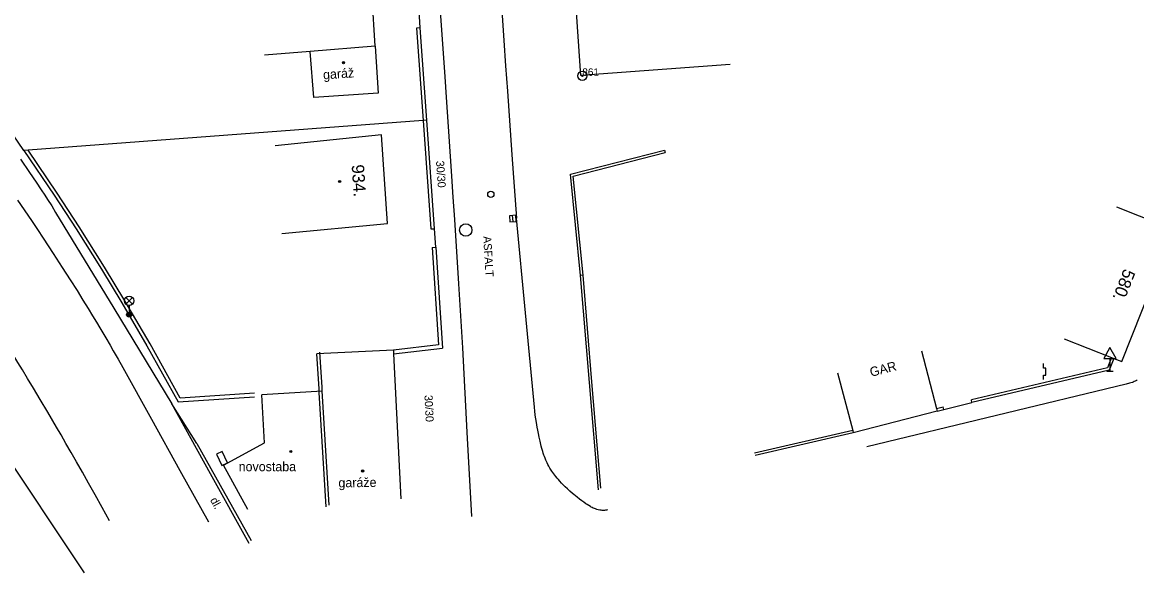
# Model space of a CAD drawing. Extents: x -538441 to -536770, y -1181008 to -1179809.
# Drawn here: x -538072 to -537982.2, y -1180978.1 to -1180933.7 of the extents above; entities that cross this region are included whole.
import ezdxf

# ---------------------------------------------------------------- set-up
doc = ezdxf.new("R2010")
doc.units = 0
for name, color, linetype in [('Vrstva 10', 7, 'Continuous'), ('Vrstva 11', 7, 'Continuous'), ('Vrstva 21', 7, 'Continuous'), ('Vrstva 23', 7, 'Continuous'), ('Vrstva 24', 7, 'Continuous'), ('Vrstva 27', 7, 'Continuous'), ('Vrstva 28', 7, 'Continuous'), ('Vrstva 33', 7, 'Continuous'), ('Vrstva 34', 7, 'Continuous'), ('Vrstva 39', 7, 'Continuous'), ('Vrstva 40', 7, 'Continuous'), ('Vrstva 41', 7, 'Continuous'), ('Vrstva 47', 7, 'Continuous'), ('Vrstva 5', 7, 'Continuous'), ('Vrstva 7', 7, 'Continuous'), ('Vrstva 8', 7, 'Continuous')]:
    doc.layers.add(name, color=color, linetype=linetype)

msp = doc.modelspace()

# ---------------------------------------------------------------- linework, layer by layer
at = {"layer": 'Vrstva 10'}
for p, q in [((-538037.959, -1180937.728), (-538038.567, -1180929.21)), ((-538037.788, -1180940.162), (-538037.959, -1180937.728)), ((-538032.92, -1180939.28), (-538032.555, -1180944.4)), ((-538032.555, -1180944.4), (-538032.19, -1180949.52)), ((-538036.84, -1180954.79), (-538037.16, -1180949.63)), ((-538031.465, -1180957.135), (-538032.19, -1180949.52)), ((-538036.52, -1180959.95), (-538036.84, -1180954.79)), ((-538030.74, -1180964.75), (-538031.465, -1180957.135)), ((-538036.15, -1180966.75), (-538036.52, -1180959.95)), ((-537983.08, -1180962.88), (-537993.522, -1180965.412)), ((-537993.522, -1180965.412), (-538003.965, -1180967.945)), ((-538066.98, -1180978.07), (-538074.76, -1180966.42)), ((-538035.78, -1180973.55), (-538036.15, -1180966.75))]:
    msp.add_line(p, q, dxfattribs=at)
for points in [[(-538033.479, -1180931.117), (-538033.204, -1180935.199), (-538033.064, -1180937.239), (-538032.92, -1180939.28)], [(-538037.16, -1180949.63), (-538037.274, -1180947.821), (-538037.384, -1180946.124), (-538037.596, -1180942.944), (-538037.788, -1180940.162)], [(-538072.37, -1180948.052), (-538071.258, -1180949.708), (-538070.775, -1180950.434)], [(-538070.775, -1180950.434), (-538070.323, -1180951.115), (-538069.901, -1180951.755), (-538069.507, -1180952.356), (-538068.774, -1180953.486), (-538068.138, -1180954.478), (-538067.587, -1180955.349), (-538067.109, -1180956.114), (-538066.694, -1180956.785), (-538066.334, -1180957.374), (-538066.021, -1180957.891), (-538065.749, -1180958.344)], [(-538069.238, -1180966.337), (-538069.936, -1180965.149), (-538070.551, -1180964.112), (-538071.093, -1180963.208), (-538071.571, -1180962.418), (-538071.991, -1180961.728), (-538072.361, -1180961.126), (-538073.012, -1180960.074), (-538073.504, -1180959.288), (-538073.876, -1180958.699), (-538074.436, -1180957.818)], [(-538065.749, -1180958.344), (-538065.278, -1180959.14), (-538064.928, -1180959.74), (-538064.668, -1180960.19), (-538064.282, -1180960.869), (-538063.9, -1180961.55), (-538061.598, -1180965.692)], [(-537982.19, -1180962.54), (-537982.241, -1180962.577), (-537982.289, -1180962.609), (-537982.336, -1180962.637), (-537982.424, -1180962.682), (-537982.503, -1180962.717), (-537982.573, -1180962.744), (-537982.698, -1180962.784), (-537982.793, -1180962.81), (-537983.08, -1180962.88)], [(-538030.61, -1180965.808), (-538030.648, -1180965.545), (-538030.674, -1180965.347), (-538030.709, -1180965.049), (-538030.74, -1180964.75)], [(-538061.598, -1180965.692), (-538059.295, -1180969.835), (-538056.992, -1180973.978)], [(-538024.85, -1180973.01), (-538024.931, -1180973.027), (-538025.009, -1180973.04), (-538025.084, -1180973.047), (-538025.157, -1180973.051), (-538025.227, -1180973.052), (-538025.295, -1180973.049), (-538025.36, -1180973.044), (-538025.423, -1180973.036), (-538025.484, -1180973.026), (-538025.602, -1180973.001), (-538025.712, -1180972.971), (-538025.814, -1180972.937), (-538025.91, -1180972.899), (-538025.999, -1180972.861), (-538026.083, -1180972.821), (-538026.161, -1180972.782), (-538026.234, -1180972.742), (-538026.37, -1180972.663), (-538026.489, -1180972.588), (-538026.593, -1180972.52), (-538026.773, -1180972.393), (-538026.908, -1180972.293), (-538027.11, -1180972.138), (-538027.31, -1180971.98), (-538027.437, -1180971.878), (-538027.557, -1180971.78), (-538027.671, -1180971.684), (-538027.887, -1180971.498), (-538028.083, -1180971.322), (-538028.259, -1180971.156), (-538028.419, -1180970.999), (-538028.563, -1180970.85), (-538028.694, -1180970.708), (-538028.813, -1180970.574), (-538028.92, -1180970.447), (-538029.017, -1180970.327), (-538029.106, -1180970.212), (-538029.186, -1180970.104), (-538029.259, -1180970.002), (-538029.325, -1180969.904), (-538029.386, -1180969.812), (-538029.494, -1180969.637), (-538029.584, -1180969.481), (-538029.658, -1180969.342), (-538029.72, -1180969.218), (-538029.772, -1180969.109), (-538029.815, -1180969.012), (-538029.887, -1180968.84), (-538029.938, -1180968.708), (-538029.973, -1180968.608), (-538030.024, -1180968.455), (-538030.07, -1180968.3), (-538030.131, -1180968.079), (-538030.186, -1180967.873), (-538030.283, -1180967.485), (-538030.361, -1180967.145), (-538030.425, -1180966.848), (-538030.477, -1180966.587), (-538030.519, -1180966.359), (-538030.554, -1180966.159), (-538030.61, -1180965.808)], [(-538064.98, -1180973.9), (-538065.571, -1180972.82), (-538066.128, -1180971.809), (-538066.655, -1180970.863), (-538067.151, -1180969.979), (-538067.619, -1180969.151), (-538068.061, -1180968.376), (-538068.477, -1180967.651), (-538068.869, -1180966.972), (-538069.238, -1180966.337)]]:
    msp.add_lwpolyline(points, dxfattribs=at)
at = {"layer": 'Vrstva 11'}
for p, q in [((-538069.31, -1180949.05), (-538064.63, -1180956.765)), ((-538064.63, -1180956.765), (-538059.95, -1180964.48)), ((-538056.835, -1180970.095), (-538059.95, -1180964.48)), ((-538057.94, -1180967.67), (-538059.95, -1180964.48)), ((-538057.94, -1180967.67), (-538053.57, -1180975.48)), ((-538053.72, -1180975.71), (-538056.835, -1180970.095))]:
    msp.add_line(p, q, dxfattribs=at)
for points in [[(-538072.134, -1180944.767), (-538071.407, -1180945.825), (-538070.868, -1180946.621), (-538070.469, -1180947.222), (-538070.173, -1180947.675)], [(-538070.173, -1180947.675), (-538069.954, -1180948.017), (-538069.629, -1180948.531), (-538069.31, -1180949.05)]]:
    msp.add_lwpolyline(points, dxfattribs=at)
at = {"layer": 'Vrstva 21'}
for radius in [0.375, 0.05]:
    msp.add_circle((-538026.88, -1180938.05), radius, dxfattribs=at)
at = {"layer": 'Vrstva 24'}
for p, q in [((-537989.729, -1180961.599), (-537989.73, -1180961.231)), ((-537989.73, -1180962.52), (-537989.729, -1180962.152)), ((-537989.546, -1180961.6), (-537989.729, -1180961.599)), ((-537989.729, -1180962.152), (-537989.546, -1180962.152)), ((-537989.546, -1180962.152), (-537989.546, -1180961.6))]:
    msp.add_line(p, q, dxfattribs=at)
msp.add_lwpolyline([(-538055.477, -1180969.224), (-538055.886, -1180968.311), (-538056.343, -1180968.516), (-538055.934, -1180969.429)], close=True, dxfattribs=at)
at = {"layer": 'Vrstva 27'}
msp.add_line((-538032.458, -1180949.794), (-538032.494, -1180949.296), dxfattribs=at)
msp.add_lwpolyline([(-538032.209, -1180949.777), (-538032.244, -1180949.278), (-538032.743, -1180949.313), (-538032.708, -1180949.812)], close=True, dxfattribs=at)
msp.add_circle((-538036.27, -1180950.47), 0.5, dxfattribs=at)
at = {"layer": 'Vrstva 28'}
msp.add_circle((-538034.25, -1180947.59), 0.25, dxfattribs=at)
at = {"layer": 'Vrstva 33'}
for p, q in [((-538063.655, -1180956.43), (-538063.125, -1180955.9)), ((-538063.655, -1180955.9), (-538063.125, -1180956.43)), ((-538063.39, -1180956.54), (-538063.39, -1180957.29))]:
    msp.add_line(p, q, dxfattribs=at)
for centre, radius in [((-538063.39, -1180956.165), 0.375), ((-538063.39, -1180957.29), 0.2), ((-538063.39, -1180957.29), 0.145), ((-538063.39, -1180957.29), 0.0876)]:
    msp.add_circle(centre, radius, dxfattribs=at)
at = {"layer": 'Vrstva 34'}
for p, q in [((-537984.374, -1180960.807), (-537984.374, -1180961.825)), ((-537984.624, -1180961.825), (-537984.124, -1180961.825))]:
    msp.add_line(p, q, dxfattribs=at)
msp.add_lwpolyline([(-537984.874, -1180960.807), (-537983.874, -1180960.807), (-537984.374, -1180959.941)], close=True, dxfattribs=at)
at = {"layer": 'Vrstva 39'}
for centre, radius in [((-538046.12, -1180936.995), 0.09), ((-538046.12, -1180936.995), 0.0398), ((-538046.434, -1180946.559), 0.09), ((-538046.434, -1180946.559), 0.0398), ((-538050.364, -1180968.311), 0.09), ((-538050.364, -1180968.311), 0.0398), ((-538044.58, -1180969.87), 0.09), ((-538044.58, -1180969.87), 0.0398)]:
    msp.add_circle(centre, radius, dxfattribs=at)
at = {"layer": 'Vrstva 5'}
for p, q in [((-538027.01, -1180938.02), (-538027.85, -1180925.58)), ((-538043.56, -1180935.65), (-538044.15, -1180926.67)), ((-538048.502, -1180939.79), (-538048.8, -1180936.09)), ((-538043.56, -1180935.65), (-538043.34, -1180939.45)), ((-538014.98, -1180937.14), (-538027.01, -1180938.02)), ((-538043.34, -1180939.45), (-538048.502, -1180939.79)), ((-538043.05, -1180942.81), (-538051.63, -1180943.69)), ((-538042.58, -1180949.94), (-538043.05, -1180942.81)), ((-537983.857, -1180948.595), (-537979.21, -1180950.44)), ((-538051.08, -1180950.75), (-538042.58, -1180949.94)), ((-537983.43, -1180961.07), (-537979.21, -1180950.44)), ((-538042.1, -1180960.15), (-538048.259, -1180960.436)), ((-538047.828, -1180963.453), (-538052.71, -1180963.75)), ((-538052.48, -1180967.61), (-538052.71, -1180963.75)), ((-537998.3, -1180965.05), (-538005.05, -1180966.81)), ((-538055.78, -1180969.42), (-538052.48, -1180967.61)), ((-538053.83, -1180972.98), (-538055.78, -1180969.42))]:
    msp.add_line(p, q, dxfattribs=at)
for points in [[(-538048.8, -1180936.09), (-538052.48, -1180936.39)], [(-538043.56, -1180935.65), (-538048.8, -1180936.09)], [(-537988.077, -1180959.225), (-537984.255, -1180960.742)], [(-538048.088, -1180963.251), (-538048.259, -1180960.436)], [(-538047.848, -1180963.121), (-538048.019, -1180960.306)], [(-538042.1, -1180960.15), (-538042.085, -1180960.449)], [(-538042.085, -1180960.449), (-538041.499, -1180972.119)], [(-537999.562, -1180960.212), (-537998.35, -1180964.857)], [(-537984.255, -1180960.742), (-537984.069, -1180960.816)], [(-537984.069, -1180960.816), (-537983.43, -1180961.07)], [(-538006.312, -1180961.972), (-538005.101, -1180966.616)], [(-538048.07, -1180963.55), (-538048.088, -1180963.251)], [(-538047.83, -1180963.42), (-538047.848, -1180963.121)], [(-538047.51, -1180972.77), (-538048.07, -1180963.55)], [(-538047.27, -1180972.64), (-538047.83, -1180963.42)], [(-537998.35, -1180964.857), (-537998.3, -1180965.05)], [(-538005.101, -1180966.616), (-538005.05, -1180966.81)]]:
    msp.add_lwpolyline(points, dxfattribs=at)
at = {"layer": 'Vrstva 7'}
for p, q in [((-538040.239, -1180934.212), (-538039.699, -1180941.643)), ((-538071.86, -1180944.07), (-538078.21, -1180934.88)), ((-538039.699, -1180941.643), (-538039.079, -1180950.381)), ((-538027.614, -1180946.121), (-538020.22, -1180944.22)), ((-538027.02, -1180954.12), (-538027.83, -1180945.97)), ((-538026.821, -1180954.104), (-538027.614, -1180946.121)), ((-538038.969, -1180951.88), (-538038.458, -1180959.716)), ((-538026.305, -1180962.76), (-538027.02, -1180954.12)), ((-538059.28, -1180964.008), (-538061.705, -1180959.641)), ((-538038.458, -1180959.716), (-538042.1, -1180960.15)), ((-538061.966, -1180959.789), (-538059.45, -1180964.32)), ((-538042.085, -1180960.449), (-538038.14, -1180959.98)), ((-537984.255, -1180960.742), (-537984.587, -1180961.579)), ((-537984.069, -1180960.816), (-537984.44, -1180961.75)), ((-537984.587, -1180961.579), (-537995.536, -1180964.155)), ((-538025.59, -1180971.4), (-538026.305, -1180962.76)), ((-538025.4, -1180971.271), (-538026.111, -1180962.688)), ((-538059.45, -1180964.32), (-538053.279, -1180963.902)), ((-538053.288, -1180963.602), (-538059.28, -1180964.008)), ((-537998.35, -1180964.857), (-537997.814, -1180964.723)), ((-538005.101, -1180966.616), (-538013.015, -1180968.435))]:
    msp.add_line(p, q, dxfattribs=at)
for points in [[(-538039.94, -1180934.19), (-538040.239, -1180934.212)], [(-538039.4, -1180941.62), (-538039.94, -1180934.19)], [(-538039.699, -1180941.643), (-538071.516, -1180944.044)], [(-538039.4, -1180941.62), (-538039.699, -1180941.643)], [(-538038.78, -1180950.36), (-538039.4, -1180941.62)], [(-538071.516, -1180944.044), (-538071.86, -1180944.07), (-538069.43, -1180947.661), (-538067.66, -1180950.38)], [(-538067.407, -1180950.218), (-538069.18, -1180947.495), (-538071.516, -1180944.044)], [(-538027.83, -1180945.97), (-538020.27, -1180944.026)], [(-538020.27, -1180944.026), (-538020.22, -1180944.22)], [(-538067.66, -1180950.38), (-538065.627, -1180953.617), (-538063.985, -1180956.327)], [(-538065.372, -1180953.459), (-538067.407, -1180950.218)], [(-538039.079, -1180950.381), (-538038.78, -1180950.36)], [(-538038.969, -1180951.88), (-538038.67, -1180951.86)], [(-538038.67, -1180951.86), (-538038.14, -1180959.98)], [(-538061.705, -1180959.641), (-538063.727, -1180956.174), (-538065.372, -1180953.459)], [(-538026.821, -1180954.104), (-538027.02, -1180954.12)], [(-538026.111, -1180962.688), (-538026.821, -1180954.104)], [(-538063.985, -1180956.327), (-538061.966, -1180959.789)], [(-537984.44, -1180961.75), (-537995.49, -1180964.35)], [(-537995.49, -1180964.35), (-537995.536, -1180964.155)], [(-537998.3, -1180965.05), (-537997.766, -1180964.917), (-537997.814, -1180964.723)], [(-538005.05, -1180966.81), (-538012.97, -1180968.63)]]:
    msp.add_lwpolyline(points, dxfattribs=at)
at = {"layer": 'Vrstva 8'}
for p, q in [((-538039.94, -1180934.19), (-538040.09, -1180931.88)), ((-538038.67, -1180951.86), (-538038.78, -1180950.36)), ((-537997.766, -1180964.917), (-537995.49, -1180964.35))]:
    msp.add_line(p, q, dxfattribs=at)

# ---------------------------------------------------------------- texts
at = {"layer": 'Vrstva 23'}
msp.add_text('861', height=0.6, dxfattribs=at).set_placement((-538026.88, -1180938.05))
at = {"layer": 'Vrstva 40'}
for s, rotation, p in [('30/30', 274.05766, (-538038.67, -1180944.91)), ('ASFALT', 273.54868, (-538034.87, -1180950.976)), ('30/30', 272.8763, (-538039.602, -1180963.77)), ('dl.', 298.61058, (-538056.89, -1180972.215))]:
    msp.add_text(s, height=0.65, rotation=rotation, dxfattribs=at).set_placement(p)
at = {"layer": 'Vrstva 41'}
for s, rotation, p in [('garáž', 3.7684, (-538047.744, -1180938.335)), ('GAR', 14.61396, (-538003.612, -1180962.301)), ('garáže', 0.75183, (-538046.524, -1180971.201))]:
    msp.add_text(s, height=0.75, rotation=rotation, dxfattribs=at).set_placement(p)
msp.add_text('novostaba', height=0.75, dxfattribs=at).set_placement((-538054.566, -1180969.898))
at = {"layer": 'Vrstva 47'}
for s, rotation, p in [('934.', 273.87559, (-538045.466, -1180945.227)), ('580.', 248.34743, (-537983.231, -1180953.525))]:
    msp.add_text(s, height=1, rotation=rotation, dxfattribs=at).set_placement(p)

doc.saveas('drawing.dxf')
